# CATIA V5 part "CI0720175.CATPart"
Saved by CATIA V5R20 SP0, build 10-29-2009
Part number: CI0720175
Bounding box of the stored display mesh (mm): x -19 to 19, y -15.457 to 205, z -19.154 to 22.707
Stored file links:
  C:\Users\Raffaele\Desktop\3D X SITO CF\BOLEX\19-INCLINED ASSEMBLY REF_CI\CI0720175.CATPart
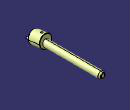
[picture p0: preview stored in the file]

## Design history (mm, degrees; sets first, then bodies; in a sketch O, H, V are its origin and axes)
Set1
  DatumSurface1 to DatumSurface16 "MANIFOLD_SOLID_BREP #389"
  DatumSurface17 to DatumSurface39 "MANIFOLD_SOLID_BREP #1118"
Body1 (main body)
